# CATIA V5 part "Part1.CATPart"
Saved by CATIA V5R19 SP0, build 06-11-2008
Part number: Part1
Bounding box of the stored display mesh (mm): x -14 to 44.5, y -14 to 14, z -24.2 to 1.5
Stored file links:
  C:\Users\sisca\Desktop\HELTEC_CASE\Part1.CATPart
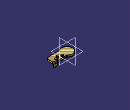
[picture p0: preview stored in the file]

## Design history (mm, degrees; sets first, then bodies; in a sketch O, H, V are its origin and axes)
Set1
  DatumCurve1 to DatumCurve8
  DatumSurface1
  DatumCurve9
  DatumCurve10
  Sketch1 on start face of Pad1, origin (0, 0, 0), H (1, 0, 0), V (0, -1, 0)
    line L1 (20.2724, 6.5) -> (30.2724, 6.5)
    line L2 (30.2724, 6.5) -> (30.2724, 4.5)
    line L3 (30.2724, 4.5) -> (20.2724, 4.5)
    line L4 (20.2724, 4.5) -> (20.2724, 6.5)
    construction line L5 (11.3248, 7) -> (40, 7)
    length L2 = 2
    distance L5 L1 = 0.5
    length L1 = 10
    horizontal: L1 H, L3 H
    vertical: L2 V, L4 V
  DatumCurve11 to DatumCurve17
  Sketch2 on end face of Pad1, origin (0, 0, 1.5), H (1, 0, 0), V (0, 1, 0)
    arc A1 centre (0, 0) radius 11.5 from (7.893, 8.3636) to (7.082, -9.0606) ccw
    point P1 (7.893, 8.3636)
    point P2 (7.082, -9.0606)
    point P3 (7.893, 8.3636)
    point P4 (11.3248, 7)
    point P5 (15.3417, 7)
    point P6 (11.3248, 7)
    point P7 (18.6583, 7)
    point P8 (15.3417, 7)
    point P9 (30.8417, 7)
    point P10 (18.6583, 7)
    point P11 (34.1583, 7)
    point P12 (30.8417, 7)
    point P13 (40, 7)
    point P14 (34.1583, 7)
    point P15 (42, 5)
    point P16 (40, 7)
    point P17 (42, -6)
    point P18 (42, 5)
    point P19 (40, -8)
    point P20 (42, -6)
    point P21 (10.1612, -8)
    point P22 (40, -8)
    point P23 (10.1612, -8)
    point P24 (7.082, -9.0606)
    arc A2 centre (11.3248, 12) radius 5 from (7.893, 8.3636) to (11.3248, 7) ccw
    line L1 (15.3417, 7) -> (11.3248, 7)
    arc A3 centre (17, 4.5) radius 3 from (18.6583, 7) to (15.3417, 7) ccw
    line L2 (30.8417, 7) -> (18.6583, 7)
    arc A4 centre (32.5, 4.5) radius 3 from (34.1583, 7) to (30.8417, 7) ccw
    line L3 (40, 7) -> (34.1583, 7)
    line L4 (42, 5) -> (40, 7)
    line L5 (42, -6) -> (42, 5)
    line L6 (40, -8) -> (42, -6)
    line L7 (10.1612, -8) -> (40, -8)
    arc A5 centre (10.1612, -13) radius 5 from (10.1612, -8) to (7.082, -9.0606) ccw
    line L8 (10.1612, -9.5) -> (40.6213, -9.5)
    arc A6 centre (10.1612, -13) radius 3.5 from (10.1612, -9.5) to (8.0058, -10.2424) ccw
    arc A7 centre (0, 0) radius 13 from (8.9225, 9.4545) to (8.0058, -10.2424) ccw
    arc A8 centre (11.3248, 12) radius 3.5 from (8.9225, 9.4545) to (11.3248, 8.5) ccw
    line L9 (14.9384, 8.5) -> (11.3248, 8.5)
    arc A9 centre (17, 4.5) radius 4.5 from (19.0616, 8.5) to (14.9384, 8.5) ccw
    line L10 (30.4384, 8.5) -> (19.0616, 8.5)
    arc A10 centre (32.5, 4.5) radius 4.5 from (34.5616, 8.5) to (30.4384, 8.5) ccw
    line L11 (40.6213, 8.5) -> (34.5616, 8.5)
    line L12 (43.5, 5.6213) -> (40.6213, 8.5)
    line L13 (43.5, -6.6213) -> (43.5, 5.6213)
    line L14 (40.6213, -9.5) -> (43.5, -6.6213)
    coincidence: P1 P3, P2 P24, P4 P6, P5 P8, P7 P10, P9 P12, P11 P14, P13 P16, P15 P18, P17 P20, P19 P22, P21 P23
  DatumSurface2
  CLDGeom1 "Tessellation.1"
Body1 (main body)
  Sketch3 on xy-plane, origin (0, 0, 0), H (1, 0, 0), V (0, 1, 0)
    line L1 (34.1583, 7) -> (40, 7)
    point P1 (40, 7)
    point P4 (40, 7)
    arc A1 centre (11.3248, 12) radius 5 from (7.893, 8.3636) to (11.3248, 7) ccw
    line L2 (40, 7) -> (42, 5)
    line L3 (42, -6) -> (40, -8)
    line L4 (10.1612, -8) -> (40, -8)
    arc A2 centre (32.5, 4.5) radius 3 from (34.1583, 7) to (30.8417, 7) ccw
    arc A3 centre (17, 4.5) radius 3 from (18.6583, 7) to (15.3417, 7) ccw
    line L5 (30.8417, 7) -> (18.6583, 7)
    line L6 (15.3417, 7) -> (11.3248, 7)
    arc A4 centre (0, 0) radius 11.5 from (7.893, 8.3636) to (7.082, -9.0606) ccw
    arc A5 centre (10.1612, -13) radius 5 from (10.1612, -8) to (7.082, -9.0606) ccw
    line L7 (42, 5) -> (42, -6)
    coincidence: P1 P4
    tangency: L5 A1, L6 A1
  Pad1: profile Sketch3, direction (0, 0, 1), length 1.5
  Sketch4 on end face of Pad1, origin (0, 0, 1.5), H (1, 0, 0), V (0, 1, 0)
    circle A1 centre (25, 0) radius 3.5
    point P1 (25, 0)
    reference projected line E1 (30.8417, 7) -> (18.6583, 7) from edge [face of Pad1 from Sketch3.L5 | end face of Pad1]
    construction line L1 (42, -5) -> (42, 5)
    radius A1 = 3.5
    distance P1 L1 = 17
    distance E1 P1 = 7
  Pocket1: profile Sketch4, direction (0, 0, -1), length 5
  Sketch5 on end face of Pad1, origin (0, 0, 1.5), H (1, 0, 0), V (0, 1, 0)
    circle A1 centre (32.5, 4.5) radius 1.65
    point P1 (32.5, 4.5)
    reference projected line E1 (42, -5) -> (42, 5) from edge [face of Pad1 from Sketch3.L7 | end face of Pad1]
    reference projected line E2 (40, 7) -> (11.3248, 7) from edge [face of Pad1 from Sketch3.L1 | end face of Pad1]
    circle A2 centre (17, 4.5) radius 1.65
    point P2 (17, 4.5)
    radius A1 = 1.65
    distance P1 E1 = 9.5
    distance P1 E2 = 2.5
    radius A2 = 1.65
    distance P1 P2 V = 0
    distance P1 P2 = 15.5
  Pocket2: profile Sketch5, direction (0, 0, -1), length 5
  Sketch6 on start face of Pad1, origin (0, 0, 0), H (1, 0, 0), V (0, -1, 0)
    arc A1 centre (0, 0) radius 8.7 from (7.3975, 4.5789) to (7.3975, -4.5789) ccw
    point P1 (7.3975, 4.5789)
    line L1 (7.3975, 4.5789) -> (7.3975, -4.5789)
    point P3 (7.3975, 4.5789)
    coincidence: P3 A1, P1 P3
    vertical: L1 V
  Pad2: profile Sketch6, direction (0, 0, -1), length 3
  Chamfer1: length 1, angle 45, on edge [face of Pad2 from Sketch6.A1 | end face of Pad2]; edge [face of Pad2 from Sketch6.L1 | end face of Pad2]
  Sketch7 on start face of Pad1, origin (0, 0, 0), H (1, 0, 0), V (0, -1, 0)
    line L1 (40, 1.75) -> (42, 1.75)
    line L2 (42, 1.75) -> (42, -1.75)
    line L3 (42, -1.75) -> (40, -1.75)
    line L4 (40, -1.75) -> (40, 1.75)
    reference projected line E1 (42, -5) -> (42, 5) from edge of DatumCurve9
    reference projected line E2 (40, 7) -> (11.3248, 7) from edge of DatumCurve10
    distance L3 L1 = 3.5
    length L1 = 2
    distance E1 L2 = 0
    distance L1 E2 = 5.25
    horizontal: L1 H, L3 H
    vertical: L2 V, L4 V
  Pad3: profile Sketch7, direction (0, 0, -1), length 4
  Chamfer2: length 0.3, angle 45, on edge [face of Pad3 from Sketch7.L3 | end face of Pad3]; edge [face of Pad3 from Sketch7.L1 | end face of Pad3]
  Pad4: profile Sketch1, direction (0, 0, -1), length 24.2
  Chamfer3: length 2, angle 30, on edge [end face of Pad1 | face of Pocket2 from Sketch5.A1]; edge [end face of Pad1 | face of Pocket2 from Sketch5.A2]
  Pad5: profile Sketch2, direction (0, 0, -1), length 1.5
  Sketch8 on face of Pad5, origin (0, 0, 1.5), H (1, 0, 0), V (0, 1, 0)
    projected line E1 (43.5, -6.6213) -> (43.5, 5.6213) from edge [face of Pad5 from Sketch2.L13 | face of Pad5]
    projected line E2 (40.6213, -9.5) -> (43.5, -6.6213) from edge [face of Pad5 from Sketch2.L14 | face of Pad5]
    projected line E3 (10.1612, -9.5) -> (40.6213, -9.5) from edge [face of Pad5 from Sketch2.L8 | face of Pad5]
    projected arc E4 centre (10.1612, -13) radius 3.5 from (10.1612, -9.5) to (8.0058, -10.2424) ccw from edge [face of Pad5 from Sketch2.A6 | face of Pad5]
    projected arc E5 centre (0, 0) radius 13 from (8.9225, 9.4545) to (8.0058, -10.2424) ccw from edge [face of Pad5 from Sketch2.A7 | face of Pad5]
    projected arc E6 centre (11.3248, 12) radius 3.5 from (8.9225, 9.4545) to (11.3248, 8.5) ccw from edge [face of Pad5 from Sketch2.A8 | face of Pad5]
    projected line E7 (14.9384, 8.5) -> (11.3248, 8.5) from edge [face of Pad5 from Sketch2.L9 | face of Pad5]
    projected arc E8 centre (17, 4.5) radius 4.5 from (19.0616, 8.5) to (14.9384, 8.5) ccw from edge [face of Pad5 from Sketch2.A9 | face of Pad5]
    projected line E9 (30.4384, 8.5) -> (19.0616, 8.5) from edge [face of Pad5 from Sketch2.L10 | face of Pad5]
    projected arc E10 centre (32.5, 4.5) radius 4.5 from (34.5616, 8.5) to (30.4384, 8.5) ccw from edge [face of Pad5 from Sketch2.A10 | face of Pad5]
    projected line E11 (40.6213, 8.5) -> (34.5616, 8.5) from edge [face of Pad5 from Sketch2.L11 | face of Pad5]
    projected line E12 (43.5, 5.6213) -> (40.6213, 8.5) from edge [face of Pad5 from Sketch2.L12 | face of Pad5]
    line L1 (44.5, 6.0355) -> (41.0355, 9.5)
    line L2 (41.0355, 9.5) -> (34.7913, 9.5)
    arc A1 centre (32.5, 4.5) radius 5.5 from (34.7913, 9.5) to (30.2087, 9.5) ccw
    line L3 (30.2087, 9.5) -> (19.2913, 9.5)
    arc A2 centre (17, 4.5) radius 5.5 from (19.2913, 9.5) to (14.7087, 9.5) ccw
    line L4 (14.7087, 9.5) -> (11.3248, 9.5)
    arc A3 centre (11.3248, 12) radius 2.5 from (9.6089, 10.1818) to (11.3248, 9.5) ccw
    arc A4 centre (0, 0) radius 14 from (9.6089, 10.1818) to (8.6216, -11.0303) ccw
    arc A5 centre (10.1612, -13) radius 2.5 from (10.1612, -10.5) to (8.6216, -11.0303) ccw
    line L5 (10.1612, -10.5) -> (41.0355, -10.5)
    line L6 (41.0355, -10.5) -> (44.5, -7.0355)
    line L7 (44.5, -7.0355) -> (44.5, 6.0355)
  Pad6: profile Sketch8, direction (0, 0, -1), length 4.5
  Chamfer4: length 0.5, angle 45, on edge [face of Pad6 from Sketch8.E2 | end face of Pad6]; edge [face of Pad6 from Sketch8.E1 | end face of Pad6]; edge [face of Pad6 from Sketch8.E3 | end face of Pad6]; edge [face of Pad6 from Sketch8.E12 | end face of Pad6]; edge [face of Pad6 from Sketch8.E11 | end face of Pad6]; edge [face of Pad6 from Sketch8.E10 | end face of Pad6]; edge [face of Pad6 from Sketch8.E9 | end face of Pad6]; edge [face of Pad6 from Sketch8.E8 | end face of Pad6]
  Fillet1: radius 1.5, on edge [face of Pad5 | face of Pad4 from Sketch1.L2]; edge [face of Pad5 | face of Pad4 from Sketch1.L4]; edge [face of Pad5 | face of Pad4 from Sketch1.L1]
  Fillet2: radius 1, on edge [face of Pad4 from Sketch1.L1 | face of Pad4 from Sketch1.L2]; edge [face of Pad4 from Sketch1.L4 | face of Pad4 from Sketch1.L1]; edge [face of Fillet1 | face of Fillet1]
  Fillet3: radius 1, on edge [face of Pad5 | face of Pad3 from Sketch7.L4]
